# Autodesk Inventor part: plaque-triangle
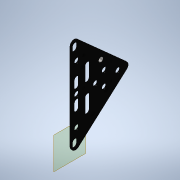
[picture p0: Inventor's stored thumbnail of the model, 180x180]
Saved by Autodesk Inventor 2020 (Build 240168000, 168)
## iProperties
Created: 2021-10
Part Number: plaque-triangle
Material: Générique
Document SubType Name: Modeling
Designer: bruno
Density: 1 g/cm^3
Appearance: Noir
Author: bruno
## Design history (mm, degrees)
sketch "Esquisse1"
  geometry: L1 (4, -0.038)-(44, -0.038); L2 (14.49, -9.788)-(19.24, -9.788); L3 (19.413, -2.288)-(23.913, -2.288); L4 (23.913, -5.788)-(19.413, -5.788); L5 (23.49, -9.788)-(19.24, -9.788); L6 (33.053, -5.788)-(37.553, -5.788); L7 (37.553, -2.288)-(33.053, -2.288); L8 (3.777, -0.038)-(-1.51, -0.038); L9 (-3.746, -5.038)-(26.254, -38.579); L10 (30.726, -38.579)-(60.726, -5.038); L11 (58.49, -0.038)-(44, -0.038); L12 (28.49, -36.579)-(28.49, 3.455); L13 (42.49, -9.788)-(37.74, -9.788); L14 (33.49, -9.788)-(37.74, -9.788); L15 (0.726, -1.038)-(-1.274, -1.038); L16 (0.726, -4.538)-(-1.274, -4.538); L17 (56.253, -1.038)-(58.253, -1.038); L18 (56.253, -4.538)-(58.253, -4.538); L19 (4, -0.038)-(3.777, -0.038); L20 (14.49, -13.288)-(23.49, -13.288); L21 (33.49, -13.288)-(42.49, -13.288); C1 r 1.75 at (48.49, -4.038); C2 r 1.75 at (8.49, -4.038); C3 r 1.75 at (28.483, -4.038); C4 r 1.75 at (28.49, -17.038); C5 r 1.75 at (28.49, -32.538); C6 r 1.75 at (33.49, -23.038); C7 r 1.75 at (23.49, -23.038); C8 r 1.5 at (40.99, -20.538); A1 r 1.75 centre (37.553, -4.038) between (37.553, -5.788) and (37.553, -2.288); A2 r 1.75 centre (23.913, -4.038) between (23.913, -5.788) and (23.913, -2.288); A3 r 1.75 centre (19.413, -4.038) between (19.413, -2.288) and (19.413, -5.788); A4 r 1.75 centre (14.49, -11.538) between (14.49, -9.788) and (14.49, -13.288); A5 r 1.75 centre (33.053, -4.038) between (33.053, -2.288) and (33.053, -5.788); A6 r 1.75 centre (23.49, -11.538) between (23.49, -13.288) and (23.49, -9.788); A7 r 3 centre (28.49, -36.579) between (26.254, -38.579) and (30.726, -38.579); A8 r 3 centre (58.49, -3.038) between (60.726, -5.038) and (58.49, -0.038); A9 r 3 centre (-1.51, -3.038) between (-1.51, -0.038) and (-3.746, -5.038); A10 r 1.75 centre (33.49, -11.538) between (33.49, -9.788) and (33.49, -13.288); A11 r 1.75 centre (42.49, -11.538) between (42.49, -13.288) and (42.49, -9.788); A12 r 1.75 centre (-1.274, -2.788) between (-1.274, -1.038) and (-1.274, -4.538); A13 r 1.75 centre (0.726, -2.788) between (0.726, -4.538) and (0.726, -1.038); A14 r 1.75 centre (56.253, -2.788) between (56.253, -1.038) and (56.253, -4.538); A15 r 1.75 centre (58.253, -2.788) between (58.253, -4.538) and (58.253, -1.038); 11 further points
  constraints: 42 end point, 31 point on circle, 23 centre point, 15 symmetric about line, 11 point on line, 9 tangent, 5 horizontal, 2 coincident, 2 equal radius, 2 parallel, 1 collinear, 1 midpoint, 1 perpendicular, 5 other
  dimensions: "d0" = 3.5 diameter of C1; "d1" = 3.5 diameter of C2; "d2" = 3.5 diameter of C3; "d3" = 3.5 diameter of A1; "d4" = 3.5 diameter of A5; "d5" = 4.5 distance of A1.centre A5.centre; "d6" = 3.5 diameter of A6; "d7" = 3 radius of A7; "d8" = 60 distance of A8.centre A9.centre; "d9" = 45 distance of L12.start A8.centre; "d10" = 45 distance of L12.start A9.centre; "d11" = 10 horizontal distance of point (8.49, -4.038) A9.centre; "d12" = 10 horizontal distance of A8.centre C1.centre; "d13" = 9 distance of A6.centre A4.centre; "d14" = 5 distance from line of L12 A6.centre; "d15" = 4 distance between parallel lines of L5 L4; "d16" = 2.25 distance between parallel lines of L1 L7; "d17" = 2.25 distance between parallel lines of L1 L3; "d18" = 3.5 diameter of C4; "d19" = 13 distance of C4.centre C3.centre; "d20" = 3.5 diameter of C5; "d21" = 15.5 distance of C5.centre C4.centre; "d22" = 3.5 diameter of C6; "d23" = 5 distance from line of L12 C6.centre; "d24" = 3.5 diameter of A13; "d25" = 3.5 diameter of A12; "d26" = 2 distance of A12.centre A13.centre; "d27" = 1 distance between parallel lines of L8 L15; "d28" = 6 vertical distance of C4.centre C6.centre; "d29" = 3 diameter of C8; "d30" = 12.5 distance from line of C8.centre L12; "d32" = 4 distance between parallel lines of L14 L6; "d33" = 4 distance from line of L1 C3.centre; "d41" = 12 vertical distance of C5.centre C8.centre
extrude "Extrusion3" join sketch "Esquisse1" distance "d42" = 1; taper "d43" = 0 deg
node "Plan de construction1"
sketch "Esquisse3"
  geometry: C1 r 1.5 at (-20.538, 40.99) reference; C2 r 3 at (-20.538, 40.99); C3 r 1.5 at (-20.538, 40.99) reference; 1 further point
  constraints: 2 coincident, 1 centre point
  dimensions: "d36" = 6 diameter of C2
extrude "Extrusion2" join sketch "Esquisse3" distance "d37" = 1.5; taper "d38" = 0 deg
node "Solide1"
